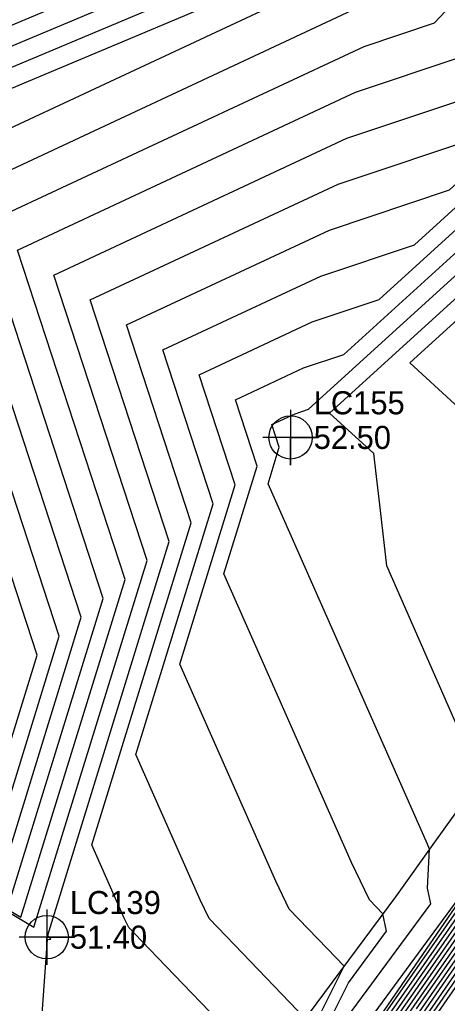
# Model space of a CAD drawing. Extents: x 2188792 to 2191981, y 386090 to 389710.
# Drawn here: x 2190090.9 to 2190137.2, y 387656.4 to 387762.9 of the extents above; entities that cross this region are included whole.
import ezdxf

# ---------------------------------------------------------------- set-up
doc = ezdxf.new("R2010")
doc.units = 0
for name, color, linetype in [('DTM Contours Major', 7, 'Continuous'), ('DTM Contours Minor', 7, 'Continuous'), ('Exist DTM Breakline', 7, 'Continuous'), ('Exist DTM Regular Point Underwater CELL', 7, 'Continuous'), ('Exist DTM Regular Point Underwater Cogo Elevation', 7, 'Continuous'), ('Exist DTM Regular Point Underwater Cogo Number', 7, 'Continuous'), ('PH Exist DTM Breakline', 7, 'Continuous')]:
    doc.layers.add(name, color=color, linetype=linetype)

msp = doc.modelspace()

# ---------------------------------------------------------------- linework, layer by layer
at = {"layer": 'DTM Contours Major'}
for points in [[(2190076.45, 387752.04), (2190123.9, 387772)], [(2190076.04, 387674.66), (2190091.05, 387665.68), (2190102.33, 387702.25), (2190090.68, 387737.92), (2190127.26, 387755.01), (2190138.57, 387758.8), (2190141.47, 387761.88), (2190144.5, 387770.18)], [(2190133.87, 387655.75), (2190142.76, 387668.49), (2190149.72, 387678.57), (2190158.03, 387690.49), (2190165.92, 387701.5), (2190174.77, 387715.42), (2190179.91, 387723.51), (2190182.41, 387727.03), (2190185.66, 387729.15), (2190187.19, 387731.57), (2190190.39, 387736.31), (2190193.76, 387741.28), (2190195, 387743.03), (2190198.41, 387748.09), (2190199.37, 387749.41), (2190202.96, 387754.24), (2190203.93, 387755.59), (2190207.5, 387760.41), (2190208.49, 387761.77), (2190212.05, 387766.57)], [(2190081.27, 387585.83), (2190091.61, 387600.99), (2190106.68, 387623.29), (2190106.53, 387625), (2190106.85, 387629.53), (2190110.17, 387629.85), (2190120.34, 387649), (2190123.14, 387654.61), (2190126.02, 387660.38), (2190124.2, 387662.28), (2190120.09, 387666.55), (2190118.63, 387669.59), (2190108.25, 387693.08), (2190114.24, 387712.49), (2190110.34, 387724.42), (2190122.58, 387730.14), (2190129.81, 387732.56), (2190148.55, 387749.61), (2190154.42, 387749.61), (2190155.27, 387750.5), (2190155.86, 387751.35), (2190160.9, 387758.19), (2190161.76, 387759.42), (2190165.94, 387763.14)], [(2190086.83, 387590.37), (2190093.48, 387600.13), (2190104.46, 387616.37), (2190110.19, 387624.77), (2190122.22, 387642.61), (2190123.96, 387645.15), (2190125.85, 387647.88), (2190141.1, 387669.76), (2190143.05, 387672.58), (2190156.4, 387691.73), (2190158.91, 387695.25), (2190172, 387715.84), (2190169.59, 387715.12), (2190165.26, 387717.22), (2190160.34, 387714.1), (2190141.79, 387731.11), (2190156.75, 387744.73), (2190158.5, 387744.73), (2190161.34, 387747.73), (2190163.33, 387750.57), (2190163.68, 387751.06), (2190167.64, 387756.72), (2190168.24, 387757.25), (2190172.95, 387763.82)], [(2190127.34, 387642.53), (2190141.89, 387663.61), (2190144.42, 387667.23), (2190156.4, 387684.56), (2190159.66, 387689.24), (2190172.92, 387707.75), (2190176.81, 387713.88), (2190179.07, 387717.44), (2190184.88, 387725.61), (2190186.38, 387726.59), (2190190.14, 387732.54), (2190191.75, 387734.92), (2190193.44, 387737.42), (2190196.91, 387742.29), (2190198.62, 387744.82), (2190201.49, 387748.8), (2190203.23, 387751.15), (2190206.18, 387755.23), (2190207.85, 387757.49), (2190210.88, 387761.68), (2190212.48, 387763.84)]]:
    msp.add_lwpolyline(points, dxfattribs=at)
at = {"layer": 'DTM Contours Minor'}
for points in [[(2190082.21, 387759.01), (2190117.52, 387773.86)], [(2190079.33, 387755.52), (2190120.71, 387772.93)], [(2190083.92, 387752.91), (2190127.09, 387771.06)], [(2190041.43, 387531.48), (2190058.13, 387555.18), (2190058.15, 387555.2), (2190058.84, 387556.18), (2190061.26, 387559.53), (2190075.95, 387580.97), (2190076.83, 387582.19), (2190085.08, 387594.3), (2190087.02, 387603.83), (2190085.63, 387618.91), (2190087.94, 387650.88), (2190087.05, 387661.98), (2190083.64, 387669.87), (2190092.46, 387664.59), (2190104.71, 387704.3), (2190094.61, 387735.22), (2190126.33, 387750.03), (2190141.35, 387755.07), (2190142.39, 387756.18), (2190147.5, 387770.18)], [(2190086.81, 387668.95), (2190095.19, 387696.11), (2190078.88, 387746.01), (2190130.07, 387769.93)], [(2190042.57, 387532.51), (2190058.4, 387554.98), (2190058.42, 387555), (2190059.07, 387555.94), (2190062.3, 387560.41), (2190076.2, 387580.7), (2190077.94, 387583.1), (2190090.49, 387601.51), (2190092.34, 387604.26), (2190090.85, 387620.43), (2190093.94, 387663.26), (2190094.29, 387663.29), (2190094.14, 387663.45), (2190094.08, 387663.52), (2190094.05, 387663.55), (2190094.03, 387663.57), (2190093.95, 387663.75), (2190107.1, 387706.35), (2190098.54, 387732.52), (2190125.39, 387745.06), (2190141.26, 387750.38), (2190143.63, 387752.53), (2190146.17, 387752.53), (2190150.45, 387767.81)], [(2190089.63, 387666.77), (2190099.95, 387700.2), (2190086.74, 387740.62), (2190128.2, 387759.98), (2190135.8, 387762.53), (2190140.54, 387767.57)], [(2190130.66, 387652.6), (2190142.09, 387669), (2190147.05, 387676.18), (2190157.38, 387690.99), (2190163.11, 387699), (2190173.95, 387716.04), (2190180.24, 387725.94), (2190181.42, 387727.6), (2190185.37, 387730.18), (2190186.01, 387731.19), (2190189.85, 387736.87), (2190193.88, 387742.83), (2190194.24, 387743.33), (2190198.33, 387749.39), (2190198.52, 387749.65), (2190202.85, 387755.48), (2190203.03, 387755.73), (2190207.37, 387761.58), (2190207.53, 387761.81), (2190211.88, 387767.66)], [(2190132.27, 387654.17), (2190142.43, 387668.75), (2190148.39, 387677.37), (2190157.7, 387690.74), (2190164.52, 387700.25), (2190174.36, 387715.73), (2190180.08, 387724.73), (2190181.92, 387727.31), (2190185.51, 387729.67), (2190186.6, 387731.38), (2190190.12, 387736.59), (2190193.82, 387742.05), (2190194.62, 387743.18), (2190198.37, 387748.74), (2190198.94, 387749.53), (2190202.9, 387754.86), (2190203.48, 387755.66), (2190207.44, 387760.99), (2190208.01, 387761.79), (2190211.97, 387767.12)], [(2190090.86, 387601.34), (2190097.12, 387610.6), (2190096.08, 387621.95), (2190098.25, 387652.02), (2190113.33, 387653.51), (2190106.72, 387660.39), (2190104.12, 387663.1), (2190102.73, 387664.55), (2190102.23, 387665.58), (2190098.72, 387673.53), (2190109.48, 387708.4), (2190102.48, 387729.82), (2190124.45, 387740.08), (2190137.44, 387744.44), (2190145.27, 387751.56), (2190152.79, 387751.56), (2190152.84, 387751.61), (2190152.88, 387751.66), (2190153.98, 387753.16), (2190156.61, 387763.69), (2190161.22, 387762.12), (2190165.02, 387765.5)], [(2190123.23, 387652.02), (2190126.49, 387658.57), (2190130.62, 387664.18), (2190130.22, 387666.05), (2190128.77, 387667.56), (2190126.83, 387671.59), (2190113.02, 387702.85), (2190116.63, 387714.54), (2190114.28, 387721.72), (2190121.64, 387725.16), (2190126, 387726.62), (2190150.19, 387748.63), (2190155.24, 387748.63), (2190156.49, 387749.95), (2190157.36, 387751.2), (2190161.45, 387756.77), (2190162.93, 387758.88), (2190166.4, 387761.96), (2190168.94, 387765.51)], [(2190125.28, 387653.38), (2190135.39, 387667.13), (2190135.04, 387668.81), (2190135.28, 387673.06), (2190135.03, 387673.6), (2190117.79, 387712.63), (2190119.01, 387716.59), (2190118.21, 387719.02), (2190120.71, 387720.19), (2190122.18, 387720.68), (2190151.83, 387747.66), (2190156.05, 387747.65), (2190157.7, 387749.39), (2190158.85, 387751.04), (2190162.01, 387755.34), (2190164.11, 387758.34), (2190166.86, 387760.78), (2190169.95, 387765.09)], [(2190125.99, 387643.58), (2190135.47, 387657.32), (2190143.09, 387668.24), (2190151.06, 387679.77), (2190158.36, 387690.24), (2190167.32, 387702.75), (2190175.18, 387715.12), (2190179.74, 387722.3), (2190182.9, 387726.75), (2190185.8, 387728.64), (2190187.78, 387731.77), (2190190.67, 387736.03), (2190193.69, 387740.51), (2190195.38, 387742.88), (2190198.45, 387747.43), (2190199.79, 387749.29), (2190203.01, 387753.63), (2190204.38, 387755.52), (2190207.57, 387759.82), (2190208.97, 387761.75), (2190212.14, 387766.02)], [(2190126.33, 387643.32), (2190137.08, 387658.89), (2190143.42, 387667.99), (2190152.4, 387680.97), (2190158.68, 387689.99), (2190168.72, 387704), (2190175.59, 387714.81), (2190179.58, 387721.08), (2190183.4, 387726.46), (2190185.95, 387728.13), (2190188.37, 387731.96), (2190190.94, 387735.76), (2190193.63, 387739.74), (2190195.76, 387742.73), (2190198.49, 387746.78), (2190200.22, 387749.17), (2190203.07, 387753.01), (2190204.83, 387755.45), (2190207.64, 387759.24), (2190209.44, 387761.73), (2190212.22, 387765.48)], [(2189984.53, 387532.74), (2189985.31, 387544.52), (2189983.47, 387548.8), (2189986.68, 387548.09), (2189986.91, 387548.12), (2189997.2, 387555.6), (2189997.78, 387556.13), (2189998.07, 387556.59), (2190001.81, 387564.06), (2190025.83, 387576.7), (2190028.7, 387578.21), (2190035.67, 387586.74), (2190061.03, 387591.74), (2190069.08, 387614.56), (2190069.86, 387615.53), (2190068.06, 387633.74), (2190066.2, 387657.23), (2190065.62, 387658.57), (2190075.79, 387674.68), (2190075.78, 387675.3), (2190088.22, 387667.86), (2190097.57, 387698.16), (2190082.81, 387743.31), (2190129.14, 387764.96)], [(2190080.16, 387584.92), (2190091.23, 387601.17), (2190101.9, 387616.94), (2190101.3, 387623.48), (2190102.55, 387640.77), (2190115.23, 387642.03), (2190119.45, 387649.98), (2190121.81, 387654.72), (2190119.3, 387657.34), (2190114.16, 387662.69), (2190111.41, 387665.55), (2190110.43, 387667.58), (2190103.49, 387683.3), (2190111.86, 387710.44), (2190106.41, 387727.12), (2190123.52, 387735.11), (2190133.63, 387738.5), (2190146.91, 387750.58), (2190153.61, 387750.58), (2190154.06, 387751.06), (2190154.37, 387751.51), (2190160.34, 387759.62), (2190160.58, 387759.97), (2190165.48, 387764.32)], [(2190124.07, 387648.18), (2190140.17, 387670.08), (2190140.15, 387670.17), (2190140.17, 387670.47), (2190140.32, 387673.15), (2190140.76, 387680.72), (2190130.64, 387703.75), (2190129.95, 387709.71), (2190129.53, 387713.39), (2190129.24, 387715.88), (2190124.45, 387720.28), (2190153.47, 387746.68), (2190156.87, 387746.68), (2190158.92, 387748.84), (2190160.34, 387750.89), (2190162.57, 387753.91), (2190165.29, 387757.8), (2190167.32, 387759.61), (2190170.95, 387764.66)], [(2190124.24, 387646.31), (2190140.77, 387670.02), (2190141.71, 387671.38), (2190156.07, 387691.98), (2190157.51, 387694), (2190165.01, 387705.8), (2190158.77, 387703.94), (2190155.12, 387699.88), (2190149.84, 387694.01), (2190148.62, 387704.67), (2190147.74, 387712.29), (2190133.12, 387725.7), (2190155.11, 387745.7), (2190157.69, 387745.7), (2190160.13, 387748.28), (2190161.83, 387750.73), (2190163.13, 387752.48), (2190166.47, 387757.26), (2190167.78, 387758.43), (2190171.95, 387764.24)], [(2190126.66, 387643.06), (2190138.68, 387660.46), (2190143.75, 387667.73), (2190153.73, 387682.17), (2190159.01, 387689.74), (2190170.12, 387705.25), (2190175.99, 387714.5), (2190179.41, 387719.87), (2190183.89, 387726.18), (2190186.09, 387727.61), (2190188.96, 387732.15), (2190191.21, 387735.48), (2190193.57, 387738.97), (2190196.15, 387742.59), (2190198.54, 387746.12), (2190200.64, 387749.05), (2190203.12, 387752.39), (2190205.28, 387755.38), (2190207.71, 387758.65), (2190209.92, 387761.72), (2190212.31, 387764.93)], [(2190127, 387642.8), (2190140.29, 387662.04), (2190144.08, 387667.48), (2190155.07, 387683.37), (2190159.34, 387689.49), (2190171.52, 387706.5), (2190176.4, 387714.19), (2190179.24, 387718.65), (2190184.39, 387725.89), (2190186.23, 387727.1), (2190189.55, 387732.35), (2190191.48, 387735.2), (2190193.51, 387738.19), (2190196.53, 387742.44), (2190198.58, 387745.47), (2190201.07, 387748.93), (2190203.18, 387751.77), (2190205.73, 387755.3), (2190207.78, 387758.07), (2190210.4, 387761.7), (2190212.39, 387764.39)], [(2190089.05, 387592.18), (2190094.22, 387599.78), (2190102.78, 387612.43), (2190110.97, 387624.44), (2190120.57, 387638.67), (2190124.63, 387644.63), (2190129.06, 387651.03), (2190141.76, 387669.26), (2190145.72, 387674.98), (2190157.05, 387691.24), (2190161.71, 387697.75), (2190173.54, 387716.35), (2190180.41, 387727.16), (2190180.93, 387727.88), (2190185.23, 387730.69), (2190185.42, 387731), (2190189.58, 387737.15), (2190191.14, 387739.45), (2190192.5, 387744.7), (2190193.66, 387749.19), (2190195.37, 387753.85), (2190196.81, 387755.98), (2190201.09, 387760.26), (2190202.98, 387763)], [(2190085.39, 387670.03), (2190092.8, 387694.06), (2190074.94, 387748.71)], [(2190127.45, 387649.46), (2190141.43, 387669.51)]]:
    msp.add_lwpolyline(points, dxfattribs=at)
at = {"layer": 'Exist DTM Breakline'}
msp.add_lwpolyline([(2189985.78, 387458.2), (2190024.04, 387505.88), (2190058.15, 387556.91), (2190090.33, 387601.59), (2190123.45, 387645.54), (2190155.63, 387692.32), (2190180.54, 387728.1)], dxfattribs=at)
at = {"layer": 'Exist DTM Regular Point Underwater CELL'}
for points in [[(2190120.23, 387720.64), (2190120.23, 387714.64), (2190120.23, 387717.64), (2190123.23, 387717.64), (2190117.23, 387717.64)], [(2190093.84, 387666.52), (2190093.84, 387660.52), (2190093.84, 387663.52), (2190096.84, 387663.52), (2190090.84, 387663.52)]]:
    msp.add_lwpolyline(points, dxfattribs=at)
for centre in [(2190120.23, 387717.64), (2190093.84, 387663.52)]:
    msp.add_circle(centre, 2.34, dxfattribs=at)
at = {"layer": 'PH Exist DTM Breakline'}
msp.add_lwpolyline([(2190199.7, 387763.89), (2190193.79, 387756.09), (2190188.11, 387748.57), (2190182.44, 387741.05), (2190176.77, 387733.53), (2190171.1, 387726), (2190165.73, 387717.92), (2190160.36, 387709.84), (2190154.99, 387701.76), (2190149.62, 387693.68), (2190144.25, 387685.6), (2190140.03, 387679.69), (2190135.8, 387673.79), (2190131.58, 387667.88), (2190127.33, 387662.15), (2190123.08, 387656.42), (2190118.82, 387650.69)], dxfattribs=at)

# ---------------------------------------------------------------- texts
at = {"layer": 'Exist DTM Regular Point Underwater Cogo Elevation'}
for s, p in [('52.50', (2190122.73, 387716.39)), ('51.40', (2190096.34, 387662.27))]:
    msp.add_text(s, height=2.5, dxfattribs=at).set_placement(p)
at = {"layer": 'Exist DTM Regular Point Underwater Cogo Number'}
for s, p in [('LC155', (2190122.73, 387720.14)), ('LC139', (2190096.34, 387666.02))]:
    msp.add_text(s, height=2.5, dxfattribs=at).set_placement(p)

doc.saveas('drawing.dxf')
